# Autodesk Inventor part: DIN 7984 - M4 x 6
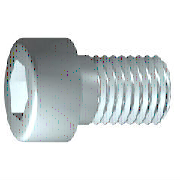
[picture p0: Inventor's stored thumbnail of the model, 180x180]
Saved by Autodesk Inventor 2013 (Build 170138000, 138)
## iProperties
IsCustomPart: 0
Created: 2012-02
Part Number: DIN 7984 - M4 x 6
Material: Stahl, weich
Description: Zylinderkopfschraube
Document SubType Name: Modeling
Standard: DIN 7984
Designer: rYan
Standard Revision: 1985
Standards Organization: DIN
Language: de-DE
Size Designation: M4 x 6
Categories: <MemberInstance><Categories><Category DisplayName="Verbindungselemente" InternalName="e4da775c-781d-43d5-af7c-5136215cf5a6" Mnemonic="FSTN"><Category DisplayNam
Density: 7.86 g/cm^3
Mass: 1.31382 g
Surface Area: 2.27551 cm^2
Volume: 0.167153 cm^3
Author: rYan
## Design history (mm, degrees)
sketch "Skizze1"
  geometry: L1 (0.333, 0)-(6, 0); L2 (6, 0)-(6, 2); L3 (6, 2)-(2.1, 2); L4 (2.1, 2)-(1.67, 2); L5 (1.67, 2)-(0, 2); L6 (0, 2)-(0, 3.5); L7 (0, 3.5)-(-2.8, 3.5); L8 (-2.8, 3.5)-(-2.8, 1.443); L9 (-2.8, 1.443)-(-0.5, 1.443); L10 (-0.5, 1.443)-(0.333, 0); L11 (-4.56, 0)-(7.76, 0) reference; L12 (0, -0.7)-(0, 4.2) reference; L13 (2.1, 2)-(0, 2)
  constraints: 22 end point, 6 parallel, 2 collinear, 2 perpendicular, 1 horizontal, 1 point on line
  dimensions: "d1" = 3.9 distance from line of L3.end L2 (= GEL); "d2" = 0.42952 distance of L4.end L3.end (computed from GAL); "d3" = 2.8 distance between parallel lines of L8 L6 (= KOH); "d4" = 2.3 distance of L8.end L9.end (= INTI); "d5" = 60 deg angle of L10 L1; "d6" = 4 diameter of L3 L1 (= GD); "d7" = 4 diameter of L5 L1 (= BDM); "d8" = 2.88675 diameter of L9 L1 (= 1.1547 x SW); "d9" = 7 diameter of L7 L1 (= KOD); "d26" = 6 distance between parallel lines of L12 L2 (= NLG)
revolve "Körper" sketch "Skizze1" stored, may be unused: angle "d10" = 90 deg
sketch "Skizze2"
  geometry: L1 (0, -4.9)-(0, 4.9) reference; L2 (-4.9, 0)-(4.9, 0) reference; L3 (1.443, 0)-(0.722, -1.25); L4 (0.722, -1.25)-(-0.722, -1.25); L5 (-0.722, -1.25)-(-1.443, 0); L6 (-1.443, 0)-(-0.722, 1.25); L7 (-0.722, 1.25)-(0.722, 1.25); L8 (0.722, 1.25)-(1.443, 0); 2 further points
  constraints: 12 end point, 1 coincident, 1 horizontal alignment, 1 point on line, 12 other
extrude "Loch" join sketch "Skizze2" stored distance "d11" = 10; taper "d12" = 0 deg
workplane "Work Plane1"
fillet "Fillet2" dims "d30" = 0.1 (= R)
body "Solid1"
fillet "Rundung1" dims "d17" = 0.4 (= RR)
feature "Gewinde" dims "d13" = 3.9 (= GEL), "d14" = 0
chamfer "Fase1" distance "d15" = 0.42941 (= -0.5 x SPD + 0.5 x GD); stored, may be unused: second distance "d16" = 0.42941 (= GUL), angle "d27" = 45 deg
other parameters: "GD" = 4 (= NND) [user parameter; used in 2 equation terms], "NLG" = 6 [user parameter; used in 1 equation term], "GEL" = 3.9 [user parameter; used in 2 equation terms], "KOD" = 7 [user parameter; used in 1 equation term], "KOH" = 2.8 [user parameter; used in 1 equation term], "INTI" = 2.3 [user parameter; used in 1 equation term], "GAL" = 0.42941 (= 0.61345 x PTC) [user parameter; used in 1 equation term], "GUL" = 0.42941 (= 0.61345 x PTC) [user parameter; used in 1 equation term], "BDM" = 4 (= NND) [user parameter; used in 1 equation term], "SW" = 2.5 [user parameter; used in 2 equation terms], "RR" = 0.4 [user parameter; used in 1 equation term], "SPD" = 3.14117 (= NND - 1.2269 x PTC) [user parameter; used in 1 equation term], "d19" = 0, "d28" = 0, "d29" = 0, "R" = 0.1 [user parameter; used in 1 equation term], "TOA" = 30 deg [user parameter], "GD1" = 3.14117 (= THREADDIA - 1.2269 x PTC) [user parameter], "THREADDIA" = 4 [user parameter; used in 1 equation term], "FAWI" = 45 deg [user parameter], "ANG" = 120 deg [user parameter], "TPU" = 14.28571 (computed from PTC) [user parameter], "PTC" = 0.7 [user parameter; used in 5 equation terms], "NND" = 4 [user parameter; used in 3 equation terms], "E0" = 2.8875 (= 1.155 x SW) [user parameter]
